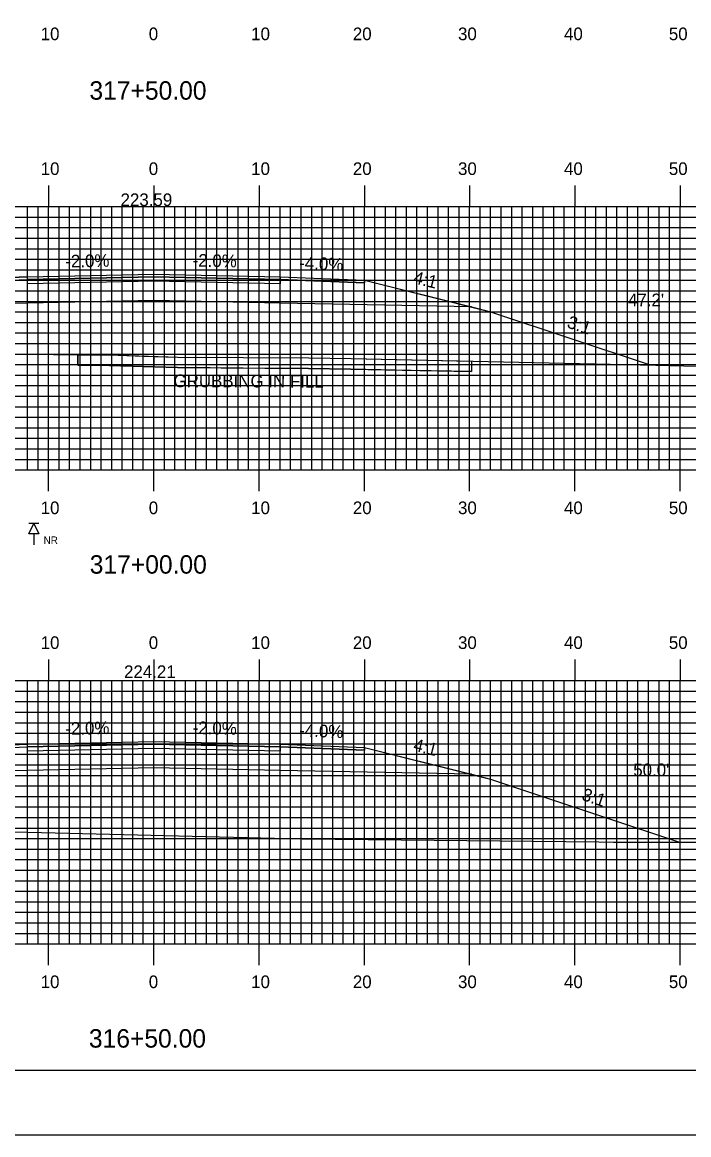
# Model space of a CAD drawing. Extents: x 1819637 to 1819981, y 442591 to 442811.
# Drawn here: x 1819790.7 to 1819854, y 442590.5 to 442696.2 of the extents above; entities that cross this region are included whole.
import ezdxf

# ---------------------------------------------------------------- set-up
doc = ezdxf.new("R2010")
doc.units = 0
for name, color, linetype in [('ANNOTATION', 7, 'Continuous'), ('BORDER', 7, 'Continuous'), ('BORING - NO REFUSAL', 7, 'Continuous'), ('D_Roadway_Centerline', 7, 'Continuous'), ('D_Roadway_Centerline_Text', 7, 'Continuous'), ('D_Roadway_Edge_Shoulder', 7, 'Continuous'), ('D_Roadway_Edge_TW', 7, 'Continuous'), ('D_Roadway_Pavement', 7, 'Continuous'), ('D_Roadway_SlopeLines', 7, 'Continuous'), ('D_Roadway_SubGrade', 7, 'Continuous'), ('D_Text_Standard', 7, 'Continuous'), ('GRUBBING IN FILL', 7, 'Continuous'), ('H_V ANNOTATION', 7, 'Continuous'), ('MAJOR', 7, 'Continuous'), ('MINOR', 7, 'Continuous'), ('PLOT BOUNDARY', 7, 'Continuous'), ('S_Roadway_Centerline', 7, 'Continuous')]:
    doc.layers.add(name, color=color, linetype=linetype)

msp = doc.modelspace()

# ---------------------------------------------------------------- linework, layer by layer
at = {"layer": 'BORDER'}
msp.add_lwpolyline([(1819653.58, 442596.67), (1819973.58, 442596.67), (1819973.58, 442806.67), (1819653.58, 442806.67)], close=True, dxfattribs=at)
at = {"layer": 'BORING - NO REFUSAL'}
for p, q in [((1819792.26, 442648.57), (1819791.3, 442648.57)), ((1819791.78, 442647.61), (1819791.78, 442646.55))]:
    msp.add_line(p, q, dxfattribs=at)
msp.add_lwpolyline([(1819791.78, 442648.57), (1819792.26, 442647.61), (1819791.3, 442647.61)], close=True, dxfattribs=at)
at = {"layer": 'D_Roadway_Centerline'}
for points in [[(1819761.34, 442666.23), (1819771.18, 442668.69), (1819773, 442669.15), (1819783.18, 442671.69), (1819791.18, 442672.01), (1819803.18, 442672.25), (1819815.18, 442672.01), (1819823.18, 442671.69), (1819833.35, 442669.15), (1819835.18, 442668.69), (1819850.33, 442663.64)], [(1819754.61, 442620.17), (1819771.18, 442624.32), (1819773, 442624.77), (1819783.18, 442627.32), (1819791.18, 442627.64), (1819803.18, 442627.88), (1819815.18, 442627.64), (1819823.18, 442627.32), (1819833.35, 442624.77), (1819835.18, 442624.32), (1819853.13, 442618.33)]]:
    msp.add_lwpolyline(points, dxfattribs=at)
at = {"layer": 'D_Roadway_Edge_Shoulder'}
for points in [[(1819791.18, 442672.01), (1819783.18, 442671.69), (1819783.18, 442671.44), (1819791.18, 442671.76)], [(1819815.18, 442672.01), (1819823.18, 442671.69), (1819823.18, 442671.44), (1819815.18, 442671.76)], [(1819791.18, 442627.64), (1819783.18, 442627.32), (1819783.18, 442627.07), (1819791.18, 442627.39)], [(1819815.18, 442627.64), (1819823.18, 442627.32), (1819823.18, 442627.07), (1819815.18, 442627.39)]]:
    msp.add_lwpolyline(points, close=True, dxfattribs=at)
at = {"layer": 'D_Roadway_Edge_TW'}
for points in [[(1819791.18, 442671.76), (1819791.18, 442672.01), (1819803.18, 442672.25), (1819815.18, 442672.01), (1819815.18, 442671.76), (1819803.18, 442672)], [(1819791.18, 442627.39), (1819791.18, 442627.64), (1819803.18, 442627.88), (1819815.18, 442627.64), (1819815.18, 442627.39), (1819803.18, 442627.63)]]:
    msp.add_lwpolyline(points, close=True, dxfattribs=at)
at = {"layer": 'D_Roadway_Pavement'}
for points in [[(1819791.18, 442671.34), (1819791.18, 442671.76), (1819803.18, 442672), (1819815.18, 442671.76), (1819815.18, 442671.34), (1819803.18, 442671.58)], [(1819791.18, 442626.97), (1819791.18, 442627.39), (1819803.18, 442627.63), (1819815.18, 442627.39), (1819815.18, 442626.97), (1819803.18, 442627.21)]]:
    msp.add_lwpolyline(points, close=True, dxfattribs=at)
at = {"layer": 'D_Roadway_SlopeLines'}
for points in [[(1819823.18, 442671.69), (1819835.18, 442668.69), (1819850.33, 442663.64)], [(1819823.18, 442627.32), (1819835.18, 442624.32), (1819853.13, 442618.33)]]:
    msp.add_lwpolyline(points, dxfattribs=at)
at = {"layer": 'D_Roadway_SubGrade'}
for points in [[(1819791.18, 442669.51), (1819773, 442669.15), (1819783.18, 442671.69), (1819783.18, 442671.44), (1819791.18, 442671.76), (1819803.18, 442672), (1819815.18, 442671.76), (1819823.18, 442671.44), (1819823.18, 442671.69), (1819833.35, 442669.15), (1819815.18, 442669.51), (1819803.18, 442669.75)], [(1819791.18, 442625.14), (1819773, 442624.77), (1819783.18, 442627.32), (1819783.18, 442627.07), (1819791.18, 442627.39), (1819803.18, 442627.63), (1819815.18, 442627.39), (1819823.18, 442627.07), (1819823.18, 442627.32), (1819833.35, 442624.77), (1819815.18, 442625.14), (1819803.18, 442625.38)]]:
    msp.add_lwpolyline(points, close=True, dxfattribs=at)
at = {"layer": 'GRUBBING IN FILL'}
for p, q in [((1819795.97, 442664.61), (1819795.97, 442663.61)), ((1819795.97, 442664.61), (1819795.97, 442663.61)), ((1819833.35, 442664), (1819833.35, 442663)), ((1819833.35, 442664), (1819833.35, 442663))]:
    msp.add_line(p, q, dxfattribs=at)
for points in [[(1819795.97, 442664.61), (1819798.98, 442664.58), (1819802.22, 442664.48), (1819803.18, 442664.45), (1819803.18, 442663.45), (1819802.2, 442663.48), (1819798.96, 442663.58), (1819795.96, 442663.61)], [(1819795.97, 442664.61), (1819798.98, 442664.58), (1819802.22, 442664.48), (1819803.18, 442664.45), (1819803.18, 442663.45), (1819802.2, 442663.48), (1819798.96, 442663.58), (1819795.96, 442663.61)], [(1819803.18, 442664.45), (1819805.45, 442664.38), (1819811.67, 442664.34), (1819817.9, 442664.3), (1819821.92, 442664.24), (1819833.35, 442664), (1819833.35, 442663), (1819827.63, 442663.12), (1819821.91, 442663.24), (1819817.89, 442663.3), (1819811.66, 442663.34), (1819805.43, 442663.38), (1819803.18, 442663.45)], [(1819803.18, 442664.45), (1819805.45, 442664.38), (1819811.67, 442664.34), (1819817.9, 442664.3), (1819821.92, 442664.24), (1819833.35, 442664), (1819833.35, 442663), (1819827.63, 442663.12), (1819821.91, 442663.24), (1819817.89, 442663.3), (1819811.66, 442663.34), (1819805.43, 442663.38), (1819803.18, 442663.45)]]:
    msp.add_lwpolyline(points, close=True, dxfattribs=at)
msp.add_lwpolyline([(1819795.96, 442663.61), (1819798.96, 442663.58), (1819805.43, 442663.38), (1819817.89, 442663.3), (1819821.91, 442663.24), (1819833.35, 442663)], dxfattribs=at)
msp.add_lwpolyline([(1819795.96, 442663.61), (1819798.96, 442663.58), (1819805.43, 442663.38), (1819817.89, 442663.3), (1819821.91, 442663.24), (1819833.35, 442663)], dxfattribs=at)
at = {"layer": 'MAJOR'}
for p, q in [((1819793.18, 442680.67), (1819793.18, 442678.67)), ((1819803.18, 442680.67), (1819803.18, 442678.67)), ((1819813.18, 442680.67), (1819813.18, 442678.67)), ((1819823.18, 442680.67), (1819823.18, 442678.67)), ((1819833.18, 442680.67), (1819833.18, 442678.67)), ((1819843.18, 442680.67), (1819843.18, 442678.67)), ((1819853.18, 442680.67), (1819853.18, 442678.67)), ((1819663.18, 442678.67), (1819943.18, 442678.67)), ((1819663.18, 442678.67), (1819943.18, 442678.67)), ((1819793.18, 442653.67), (1819793.18, 442678.67)), ((1819803.18, 442653.67), (1819803.18, 442678.67)), ((1819813.18, 442653.67), (1819813.18, 442678.67)), ((1819823.18, 442653.67), (1819823.18, 442678.67)), ((1819833.18, 442653.67), (1819833.18, 442678.67)), ((1819843.18, 442653.67), (1819843.18, 442678.67)), ((1819853.18, 442653.67), (1819853.18, 442678.67)), ((1819663.18, 442673.67), (1819943.18, 442673.67)), ((1819663.18, 442668.67), (1819943.18, 442668.67)), ((1819663.18, 442663.67), (1819943.18, 442663.67)), ((1819663.18, 442658.67), (1819943.18, 442658.67)), ((1819663.18, 442653.67), (1819943.18, 442653.67)), ((1819663.18, 442653.67), (1819943.18, 442653.67)), ((1819793.18, 442651.66), (1819793.18, 442653.67)), ((1819803.18, 442651.66), (1819803.18, 442653.67)), ((1819813.18, 442651.66), (1819813.18, 442653.67)), ((1819823.18, 442651.66), (1819823.18, 442653.67)), ((1819833.18, 442651.66), (1819833.18, 442653.67)), ((1819843.18, 442651.66), (1819843.18, 442653.67)), ((1819853.18, 442651.66), (1819853.18, 442653.67)), ((1819793.18, 442635.67), (1819793.18, 442633.67)), ((1819803.18, 442635.67), (1819803.18, 442633.67)), ((1819813.18, 442635.67), (1819813.18, 442633.67)), ((1819823.18, 442635.67), (1819823.18, 442633.67)), ((1819833.18, 442635.67), (1819833.18, 442633.67)), ((1819843.18, 442635.67), (1819843.18, 442633.67)), ((1819853.18, 442635.67), (1819853.18, 442633.67)), ((1819663.18, 442633.67), (1819943.18, 442633.67)), ((1819663.18, 442633.67), (1819943.18, 442633.67)), ((1819793.18, 442608.67), (1819793.18, 442633.67)), ((1819803.18, 442608.67), (1819803.18, 442633.67)), ((1819813.18, 442608.67), (1819813.18, 442633.67)), ((1819823.18, 442608.67), (1819823.18, 442633.67)), ((1819833.18, 442608.67), (1819833.18, 442633.67)), ((1819843.18, 442608.67), (1819843.18, 442633.67)), ((1819853.18, 442608.67), (1819853.18, 442633.67)), ((1819663.18, 442628.67), (1819943.18, 442628.67)), ((1819663.18, 442623.67), (1819943.18, 442623.67)), ((1819663.18, 442618.67), (1819943.18, 442618.67)), ((1819663.18, 442613.67), (1819943.18, 442613.67)), ((1819663.18, 442608.67), (1819943.18, 442608.67)), ((1819663.18, 442608.67), (1819943.18, 442608.67)), ((1819793.18, 442606.66), (1819793.18, 442608.67)), ((1819803.18, 442606.66), (1819803.18, 442608.67)), ((1819813.18, 442606.66), (1819813.18, 442608.67)), ((1819823.18, 442606.66), (1819823.18, 442608.67)), ((1819833.18, 442606.66), (1819833.18, 442608.67)), ((1819843.18, 442606.66), (1819843.18, 442608.67)), ((1819853.18, 442606.66), (1819853.18, 442608.67))]:
    msp.add_line(p, q, dxfattribs=at)
at = {"layer": 'MINOR'}
for p, q in [((1819791.18, 442653.67), (1819791.18, 442678.67)), ((1819792.18, 442653.67), (1819792.18, 442678.67)), ((1819794.18, 442653.67), (1819794.18, 442678.67)), ((1819795.18, 442653.67), (1819795.18, 442678.67)), ((1819796.18, 442653.67), (1819796.18, 442678.67)), ((1819797.18, 442653.67), (1819797.18, 442678.67)), ((1819798.18, 442653.67), (1819798.18, 442678.67)), ((1819799.18, 442653.67), (1819799.18, 442678.67)), ((1819800.18, 442653.67), (1819800.18, 442678.67)), ((1819801.18, 442653.67), (1819801.18, 442678.67)), ((1819802.18, 442653.67), (1819802.18, 442678.67)), ((1819804.18, 442653.67), (1819804.18, 442678.67)), ((1819805.18, 442653.67), (1819805.18, 442678.67)), ((1819806.18, 442653.67), (1819806.18, 442678.67)), ((1819807.18, 442653.67), (1819807.18, 442678.67)), ((1819808.18, 442653.67), (1819808.18, 442678.67)), ((1819809.18, 442653.67), (1819809.18, 442678.67)), ((1819810.18, 442653.67), (1819810.18, 442678.67)), ((1819811.18, 442653.67), (1819811.18, 442678.67)), ((1819812.18, 442653.67), (1819812.18, 442678.67)), ((1819814.18, 442653.67), (1819814.18, 442678.67)), ((1819815.18, 442653.67), (1819815.18, 442678.67)), ((1819816.18, 442653.67), (1819816.18, 442678.67)), ((1819817.18, 442653.67), (1819817.18, 442678.67)), ((1819818.18, 442653.67), (1819818.18, 442678.67)), ((1819819.18, 442653.67), (1819819.18, 442678.67)), ((1819820.18, 442653.67), (1819820.18, 442678.67)), ((1819821.18, 442653.67), (1819821.18, 442678.67)), ((1819822.18, 442653.67), (1819822.18, 442678.67)), ((1819824.18, 442653.67), (1819824.18, 442678.67)), ((1819825.18, 442653.67), (1819825.18, 442678.67)), ((1819826.18, 442653.67), (1819826.18, 442678.67)), ((1819827.18, 442653.67), (1819827.18, 442678.67)), ((1819828.18, 442653.67), (1819828.18, 442678.67)), ((1819829.18, 442653.67), (1819829.18, 442678.67)), ((1819830.18, 442653.67), (1819830.18, 442678.67)), ((1819831.18, 442653.67), (1819831.18, 442678.67)), ((1819832.18, 442653.67), (1819832.18, 442678.67)), ((1819834.18, 442653.67), (1819834.18, 442678.67)), ((1819835.18, 442653.67), (1819835.18, 442678.67)), ((1819836.18, 442653.67), (1819836.18, 442678.67)), ((1819837.18, 442653.67), (1819837.18, 442678.67)), ((1819838.18, 442653.67), (1819838.18, 442678.67)), ((1819839.18, 442653.67), (1819839.18, 442678.67)), ((1819840.18, 442653.67), (1819840.18, 442678.67)), ((1819841.18, 442653.67), (1819841.18, 442678.67)), ((1819842.18, 442653.67), (1819842.18, 442678.67)), ((1819844.18, 442653.67), (1819844.18, 442678.67)), ((1819845.18, 442653.67), (1819845.18, 442678.67)), ((1819846.18, 442653.67), (1819846.18, 442678.67)), ((1819847.18, 442653.67), (1819847.18, 442678.67)), ((1819848.18, 442653.67), (1819848.18, 442678.67)), ((1819849.18, 442653.67), (1819849.18, 442678.67)), ((1819850.18, 442653.67), (1819850.18, 442678.67)), ((1819851.18, 442653.67), (1819851.18, 442678.67)), ((1819852.18, 442653.67), (1819852.18, 442678.67)), ((1819663.18, 442677.67), (1819943.18, 442677.67)), ((1819663.18, 442676.67), (1819943.18, 442676.67)), ((1819663.18, 442675.67), (1819943.18, 442675.67)), ((1819663.18, 442674.67), (1819943.18, 442674.67)), ((1819663.18, 442672.67), (1819943.18, 442672.67)), ((1819663.18, 442671.67), (1819943.18, 442671.67)), ((1819663.18, 442670.67), (1819943.18, 442670.67)), ((1819663.18, 442669.67), (1819943.18, 442669.67)), ((1819663.18, 442667.67), (1819943.18, 442667.67)), ((1819663.18, 442666.67), (1819943.18, 442666.67)), ((1819663.18, 442665.67), (1819943.18, 442665.67)), ((1819663.18, 442664.67), (1819943.18, 442664.67)), ((1819663.18, 442662.67), (1819943.18, 442662.67)), ((1819663.18, 442661.67), (1819943.18, 442661.67)), ((1819663.18, 442660.67), (1819943.18, 442660.67)), ((1819663.18, 442659.67), (1819943.18, 442659.67)), ((1819663.18, 442657.67), (1819943.18, 442657.67)), ((1819663.18, 442656.67), (1819943.18, 442656.67)), ((1819663.18, 442655.67), (1819943.18, 442655.67)), ((1819663.18, 442654.67), (1819943.18, 442654.67)), ((1819791.18, 442608.67), (1819791.18, 442633.67)), ((1819792.18, 442608.67), (1819792.18, 442633.67)), ((1819794.18, 442608.67), (1819794.18, 442633.67)), ((1819795.18, 442608.67), (1819795.18, 442633.67)), ((1819796.18, 442608.67), (1819796.18, 442633.67)), ((1819797.18, 442608.67), (1819797.18, 442633.67)), ((1819798.18, 442608.67), (1819798.18, 442633.67)), ((1819799.18, 442608.67), (1819799.18, 442633.67)), ((1819800.18, 442608.67), (1819800.18, 442633.67)), ((1819801.18, 442608.67), (1819801.18, 442633.67)), ((1819802.18, 442608.67), (1819802.18, 442633.67)), ((1819804.18, 442608.67), (1819804.18, 442633.67)), ((1819805.18, 442608.67), (1819805.18, 442633.67)), ((1819806.18, 442608.67), (1819806.18, 442633.67)), ((1819807.18, 442608.67), (1819807.18, 442633.67)), ((1819808.18, 442608.67), (1819808.18, 442633.67)), ((1819809.18, 442608.67), (1819809.18, 442633.67)), ((1819810.18, 442608.67), (1819810.18, 442633.67)), ((1819811.18, 442608.67), (1819811.18, 442633.67)), ((1819812.18, 442608.67), (1819812.18, 442633.67)), ((1819814.18, 442608.67), (1819814.18, 442633.67)), ((1819815.18, 442608.67), (1819815.18, 442633.67)), ((1819816.18, 442608.67), (1819816.18, 442633.67)), ((1819817.18, 442608.67), (1819817.18, 442633.67)), ((1819818.18, 442608.67), (1819818.18, 442633.67)), ((1819819.18, 442608.67), (1819819.18, 442633.67)), ((1819820.18, 442608.67), (1819820.18, 442633.67)), ((1819821.18, 442608.67), (1819821.18, 442633.67)), ((1819822.18, 442608.67), (1819822.18, 442633.67)), ((1819824.18, 442608.67), (1819824.18, 442633.67)), ((1819825.18, 442608.67), (1819825.18, 442633.67)), ((1819826.18, 442608.67), (1819826.18, 442633.67)), ((1819827.18, 442608.67), (1819827.18, 442633.67)), ((1819828.18, 442608.67), (1819828.18, 442633.67)), ((1819829.18, 442608.67), (1819829.18, 442633.67)), ((1819830.18, 442608.67), (1819830.18, 442633.67)), ((1819831.18, 442608.67), (1819831.18, 442633.67)), ((1819832.18, 442608.67), (1819832.18, 442633.67)), ((1819834.18, 442608.67), (1819834.18, 442633.67)), ((1819835.18, 442608.67), (1819835.18, 442633.67)), ((1819836.18, 442608.67), (1819836.18, 442633.67)), ((1819837.18, 442608.67), (1819837.18, 442633.67)), ((1819838.18, 442608.67), (1819838.18, 442633.67)), ((1819839.18, 442608.67), (1819839.18, 442633.67)), ((1819840.18, 442608.67), (1819840.18, 442633.67)), ((1819841.18, 442608.67), (1819841.18, 442633.67)), ((1819842.18, 442608.67), (1819842.18, 442633.67)), ((1819844.18, 442608.67), (1819844.18, 442633.67)), ((1819845.18, 442608.67), (1819845.18, 442633.67)), ((1819846.18, 442608.67), (1819846.18, 442633.67)), ((1819847.18, 442608.67), (1819847.18, 442633.67)), ((1819848.18, 442608.67), (1819848.18, 442633.67)), ((1819849.18, 442608.67), (1819849.18, 442633.67)), ((1819850.18, 442608.67), (1819850.18, 442633.67)), ((1819851.18, 442608.67), (1819851.18, 442633.67)), ((1819852.18, 442608.67), (1819852.18, 442633.67)), ((1819663.18, 442632.67), (1819943.18, 442632.67)), ((1819663.18, 442631.67), (1819943.18, 442631.67)), ((1819663.18, 442630.67), (1819943.18, 442630.67)), ((1819663.18, 442629.67), (1819943.18, 442629.67)), ((1819663.18, 442627.67), (1819943.18, 442627.67)), ((1819663.18, 442626.67), (1819943.18, 442626.67)), ((1819663.18, 442625.67), (1819943.18, 442625.67)), ((1819663.18, 442624.67), (1819943.18, 442624.67)), ((1819663.18, 442622.67), (1819943.18, 442622.67)), ((1819663.18, 442621.67), (1819943.18, 442621.67)), ((1819663.18, 442620.67), (1819943.18, 442620.67)), ((1819663.18, 442619.67), (1819943.18, 442619.67)), ((1819663.18, 442617.67), (1819943.18, 442617.67)), ((1819663.18, 442616.67), (1819943.18, 442616.67)), ((1819663.18, 442615.67), (1819943.18, 442615.67)), ((1819663.18, 442614.67), (1819943.18, 442614.67)), ((1819663.18, 442612.67), (1819943.18, 442612.67)), ((1819663.18, 442611.67), (1819943.18, 442611.67)), ((1819663.18, 442610.67), (1819943.18, 442610.67)), ((1819663.18, 442609.67), (1819943.18, 442609.67))]:
    msp.add_line(p, q, dxfattribs=at)
at = {"layer": 'PLOT BOUNDARY'}
msp.add_lwpolyline([(1819637.39, 442590.55), (1819977.39, 442590.55), (1819977.39, 442810.55), (1819637.39, 442810.55)], close=True, dxfattribs=at)
at = {"layer": 'S_Roadway_Centerline'}
for points in [[(1819663.18, 442669.11), (1819663.36, 442669.1), (1819672.73, 442669.08), (1819681.25, 442668.96), (1819695, 442668.76), (1819697.67, 442668.76), (1819699.01, 442668.7), (1819706.58, 442669.07), (1819715.51, 442669.29), (1819718.52, 442669.16), (1819731.65, 442668.07), (1819739.41, 442667.9), (1819762.61, 442666.13), (1819764.92, 442665.92), (1819770.34, 442665.53), (1819782.62, 442664.8), (1819788.26, 442664.67), (1819798.98, 442664.58), (1819805.45, 442664.38), (1819817.9, 442664.3), (1819821.92, 442664.24), (1819850.87, 442663.63), (1819860.19, 442663.38)], [(1819663.18, 442623.62), (1819666.48, 442623.49), (1819670.71, 442623.16), (1819676.4, 442622.65), (1819688.03, 442622.65), (1819693.91, 442622.62), (1819697.22, 442622.47), (1819708.98, 442622.2), (1819710.94, 442622.14), (1819711.72, 442622.12), (1819727.84, 442621.48), (1819733.69, 442621.2), (1819744.35, 442620.68), (1819749.16, 442620.4), (1819761.15, 442619.9), (1819777.48, 442619.58), (1819779.45, 442619.55), (1819808.13, 442618.86), (1819817.28, 442618.63), (1819845.46, 442618.36), (1819846.85, 442618.34), (1819857.51, 442618.33)]]:
    msp.add_lwpolyline(points, dxfattribs=at)

# ---------------------------------------------------------------- texts
at = {"layer": 'ANNOTATION'}
for s, rotation, p in [('-2.0%', 1.1458, (1819794.78, 442672.88)), ('-2.0%', 358.8542, (1819806.86, 442672.98)), ('-4.0%', 357.7094, (1819816.97, 442672.74)), ('4:1', 345.9638, (1819827.77, 442671.41)), ('3:1', 341.5652, (1819842.36, 442667.21)), ('-2.0%', 1.1458, (1819794.78, 442628.51)), ('-2.0%', 358.8542, (1819806.86, 442628.6)), ('-4.0%', 357.7094, (1819816.97, 442628.37)), ('4:1', 345.9638, (1819827.77, 442627.03)), ('3:1', 341.5652, (1819843.76, 442622.36))]:
    msp.add_text(s, height=1.2, rotation=rotation, dxfattribs=at).set_placement(p)
at = {"layer": 'BORING - NO REFUSAL'}
msp.add_text('NR', height=0.7, dxfattribs=at).set_placement((1819792.71, 442646.65))
at = {"layer": 'D_Roadway_Centerline'}
for s, p in [('C', (1819803.17, 442672.25)), ('L', (1819803.18, 442672.24)), ('C', (1819803.17, 442627.88)), ('L', (1819803.18, 442627.87))]:
    msp.add_text(s, height=0.0146, dxfattribs=at).set_placement(p)
at = {"layer": 'D_Roadway_Centerline_Text'}
for s, p in [('223.59', (1819800.02, 442678.72)), ('224.21', (1819800.35, 442633.91))]:
    msp.add_text(s, height=1.2, dxfattribs=at).set_placement(p)
at = {"layer": 'D_Text_Standard'}
for s, p in [("47.2'", (1819848.23, 442669.21)), ("50.0'", (1819848.73, 442624.59))]:
    msp.add_text(s, height=1.2, dxfattribs=at).set_placement(p)
at = {"layer": 'GRUBBING IN FILL'}
msp.add_text('GRUBBING IN FILL', height=1.2, rotation=359.8053, dxfattribs=at).set_placement((1819805.05, 442661.53))
at = {"layer": 'H_V ANNOTATION'}
for s, height, p in [('10', 1.2, (1819792.43, 442694.47)), ('0', 1.2, (1819802.7, 442694.47)), ('10', 1.2, (1819812.43, 442694.47)), ('20', 1.2, (1819822.09, 442694.47)), ('30', 1.2, (1819832.08, 442694.47)), ('40', 1.2, (1819842.15, 442694.47)), ('50', 1.2, (1819852.11, 442694.47)), ('317+50.00', 1.75, (1819797.06, 442688.82)), ('10', 1.2, (1819792.43, 442681.67)), ('0', 1.2, (1819802.7, 442681.67)), ('10', 1.2, (1819812.43, 442681.67)), ('20', 1.2, (1819822.09, 442681.67)), ('30', 1.2, (1819832.08, 442681.67)), ('40', 1.2, (1819842.15, 442681.67)), ('50', 1.2, (1819852.11, 442681.67)), ('10', 1.2, (1819792.43, 442649.47)), ('0', 1.2, (1819802.7, 442649.47)), ('10', 1.2, (1819812.43, 442649.47)), ('20', 1.2, (1819822.09, 442649.47)), ('30', 1.2, (1819832.08, 442649.47)), ('40', 1.2, (1819842.15, 442649.47)), ('50', 1.2, (1819852.11, 442649.47)), ('317+00.00', 1.75, (1819797.09, 442643.82)), ('10', 1.2, (1819792.43, 442636.67)), ('0', 1.2, (1819802.7, 442636.67)), ('10', 1.2, (1819812.43, 442636.67)), ('20', 1.2, (1819822.09, 442636.67)), ('30', 1.2, (1819832.08, 442636.67)), ('40', 1.2, (1819842.15, 442636.67)), ('50', 1.2, (1819852.11, 442636.67)), ('10', 1.2, (1819792.43, 442604.47)), ('0', 1.2, (1819802.7, 442604.47)), ('10', 1.2, (1819812.43, 442604.47)), ('20', 1.2, (1819822.09, 442604.47)), ('30', 1.2, (1819832.08, 442604.47)), ('40', 1.2, (1819842.15, 442604.47)), ('50', 1.2, (1819852.11, 442604.47)), ('316+50.00', 1.75, (1819797.01, 442598.82))]:
    msp.add_text(s, height=height, dxfattribs=at).set_placement(p)

doc.saveas('drawing.dxf')
